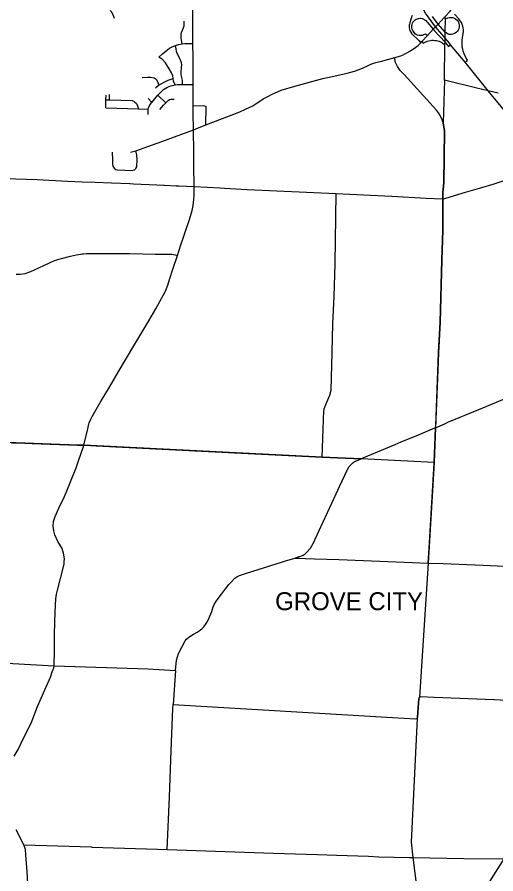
# Model space of a CAD drawing. Extents: x 1755200 to 1902939, y 644115 to 788070.
# Drawn here: x 1782951 to 1796306, y 677595 to 701476 of the extents above; entities that cross this region are included whole.
import ezdxf

# ---------------------------------------------------------------- set-up
doc = ezdxf.new("R2010")
doc.units = 0
for name, color, linetype in [('GM_X_City_Street', 7, 'Continuous'), ('GM_X_Corporation_Text', 7, 'Continuous'), ('GM_X_County_Road', 7, 'Continuous'), ('GM_X_Interchange_Ramps', 7, 'Continuous'), ('GM_X_Interstate_Route', 7, 'Continuous'), ('GM_X_Township', 7, 'Continuous'), ('GM_X_Township_Road', 7, 'Continuous'), ('GM_X_US_Route', 7, 'Continuous')]:
    doc.layers.add(name, color=color, linetype=linetype)

msp = doc.modelspace()

# ---------------------------------------------------------------- linework, layer by layer
at = {"layer": 'GM_X_City_Street'}
for points in [[(1787860, 699018), (1787858, 699597), (1787860, 700358), (1787857, 700738), (1787852, 701242), (1787854, 701665), (1787855, 702336), (1787857, 703006), (1787855, 703286)], [(1793741, 700437), (1793752, 700441), (1793845, 700487), (1793927, 700535), (1794011, 700592), (1794134, 700688), (1794214, 700764), (1794240, 700797), (1794396, 700960), (1794557, 701136), (1794621, 701208), (1794693, 701283), (1794864, 701465), (1794893, 701495), (1795030, 701641), (1795063, 701678), (1795126, 701755), (1795195, 701840), (1795261, 701935), (1795301, 702007), (1795333, 702066)], [(1785663, 701434), (1785634, 701537), (1785581, 701622), (1785551, 701659)], [(1787558, 700734), (1787537, 700830), (1787529, 700891), (1787526, 700956), (1787530, 701005), (1787537, 701045), (1787566, 701117), (1787607, 701233), (1787615, 701295), (1787613, 701362)], [(1786904, 700363), (1787009, 700452), (1787107, 700539), (1787201, 700608), (1787291, 700659), (1787371, 700689), (1787457, 700713), (1787558, 700734), (1787630, 700741), (1787857, 700738)], [(1787568, 699600), (1787565, 699703), (1787558, 699757), (1787529, 699867), (1787526, 699907), (1787530, 699946), (1787540, 700071), (1787544, 700150), (1787537, 700203), (1787516, 700260), (1787490, 700314), (1787410, 700486), (1787371, 700689)], [(1787874, 698335), (1788217, 698471), (1788682, 698648), (1789167, 698839), (1789320, 698907), (1789523, 699005), (1789815, 699194), (1789942, 699267), (1790064, 699333), (1790216, 699398), (1790319, 699438), (1790694, 699548), (1791479, 699763), (1791782, 699829), (1792162, 699917), (1792363, 699973), (1792488, 700015), (1792602, 700064), (1792727, 700122), (1792821, 700163), (1792957, 700208), (1793151, 700262), (1793486, 700349), (1793652, 700400), (1793741, 700437)], [(1787359, 699591), (1787316, 699688), (1787305, 699768), (1787296, 699835), (1787257, 699924), (1787193, 700037), (1787087, 700199), (1786996, 700308), (1786904, 700363)], [(1794824, 696413), (1794825, 696594), (1794834, 696685), (1794851, 696855), (1794873, 698294), (1794837, 698528), (1794811, 698613), (1794734, 698773), (1794654, 698882), (1793750, 699877), (1793637, 699992), (1793560, 700096), (1793541, 700135), (1793499, 700228), (1793486, 700349)], [(1786436, 699794), (1786590, 699806), (1786672, 699801), (1786772, 699784), (1786828, 699747), (1786867, 699684), (1786902, 699576)], [(1786813, 699503), (1786890, 699568), (1786902, 699576), (1786972, 699621), (1787067, 699672), (1787164, 699720), (1787305, 699768)], [(1786606, 698762), (1786608, 698906), (1786608, 698916), (1786623, 698964), (1786650, 699034), (1786706, 699100), (1786875, 699296), (1786878, 699299), (1787035, 699454), (1787143, 699521), (1787241, 699558), (1787359, 699591), (1787427, 699599), (1787568, 699600), (1787858, 699597)], [(1785424, 698946), (1785425, 699168), (1785432, 699299)], [(1785525, 699166), (1785529, 699315)], [(1786875, 699296), (1787102, 699091)], [(1785425, 699168), (1785525, 699166), (1786160, 699148), (1786228, 699113), (1786284, 699069), (1786311, 699004), (1786334, 698915)], [(1786602, 699211), (1786706, 699100)], [(1786932, 698898), (1787036, 699025), (1787102, 699091), (1787164, 699155), (1787197, 699177), (1787241, 699190), (1787265, 699190), (1787333, 699187)], [(1787874, 698334), (1787874, 698335), (1787863, 698796), (1787860, 699008), (1787860, 699018)], [(1787860, 699008), (1788180, 699002), (1788221, 698982)], [(1785424, 698946), (1786334, 698915), (1786608, 698906)], [(1788217, 698471), (1788221, 698982)], [(1786109, 697716), (1786264, 697748), (1786593, 697867), (1786985, 698008), (1787874, 698335)], [(1787878, 697701), (1787874, 698334)], [(1785601, 697716), (1785608, 697498), (1785608, 697405), (1785608, 697365), (1785620, 697318), (1785657, 697268), (1785707, 697231), (1785753, 697219), (1785960, 697210), (1786164, 697200), (1786225, 697219), (1786264, 697254), (1786292, 697299), (1786302, 697505), (1786292, 697627), (1786264, 697748)], [(1787886, 696753), (1787886, 696753), (1787877, 697338), (1787878, 697696), (1787878, 697701)], [(1794815, 696413), (1794824, 696413), (1794882, 696423), (1795150, 696503), (1795462, 696597), (1795846, 696710), (1796227, 696823), (1796396, 696877), (1796541, 696924)], [(1787465, 696773), (1787886, 696753)], [(1787581, 695318), (1787644, 695510), (1787755, 695837), (1787831, 696083), (1787865, 696227), (1787884, 696389), (1787886, 696506), (1787886, 696753)], [(1787886, 696753), (1788614, 696715), (1788733, 696708)], [(1788733, 696708), (1789370, 696675), (1791855, 696557), (1792612, 696521), (1793399, 696481), (1794364, 696432), (1794815, 696413)], [(1791515, 690529), (1791520, 690559), (1791534, 690600), (1791565, 690676), (1791675, 690939), (1791710, 691076), (1791741, 692131), (1791760, 692924), (1791791, 693686), (1791820, 694601), (1791855, 696557)], [(1794723, 692465), (1794750, 692977), (1794796, 694700), (1794822, 695537), (1794824, 696413)], [(1787206, 694162), (1787215, 694190), (1787299, 694452), (1787421, 694829), (1787518, 695126), (1787581, 695318)], [(1787268, 694866), (1787316, 694859), (1787360, 694848), (1787421, 694829)], [(1794627, 690096), (1794704, 692111), (1794706, 692149)], [(1794896, 690150), (1794967, 690182), (1795830, 690539), (1796659, 690885), (1796910, 690990), (1797053, 691047)], [(1791461, 689213), (1791511, 690507), (1791515, 690529)], [(1792546, 689167), (1792624, 689200), (1793496, 689565), (1793662, 689634), (1794151, 689836), (1794604, 690023)], [(1785153, 689525), (1789400, 689315)], [(1789400, 689315), (1791461, 689213), (1792546, 689167)], [(1791954, 688409), (1792155, 688846), (1792210, 688952), (1792312, 689056), (1792364, 689086), (1792418, 689112), (1792546, 689167)], [(1794416, 686257), (1794442, 686678)], [(1793981, 686274), (1794416, 686257)], [(1794416, 686257), (1794416, 686257), (1794840, 686242)], [(1796257, 682451), (1796936, 682422), (1798693, 682335), (1798738, 682332)]]:
    msp.add_lwpolyline(points, dxfattribs=at)
at = {"layer": 'GM_X_County_Road'}
for points in [[(1782535, 694298), (1782550, 695153), (1782591, 696469), (1782608, 696832), (1782612, 696920), (1782619, 696976), (1783507, 696946), (1784356, 696907), (1784769, 696885), (1785129, 696875), (1785584, 696857), (1786091, 696836), (1786195, 696829), (1786848, 696802), (1787044, 696794)], [(1787044, 696794), (1787062, 696793), (1787389, 696777), (1787465, 696773)], [(1782920, 694307), (1783033, 694312), (1783111, 694323), (1783176, 694333), (1783333, 694386), (1783575, 694498), (1783695, 694551), (1783871, 694632), (1783993, 694688), (1784059, 694711), (1784115, 694732), (1784191, 694752), (1784440, 694810), (1784605, 694851), (1784718, 694873), (1784755, 694880), (1784804, 694882), (1784877, 694883), (1785289, 694884), (1786094, 694888), (1786813, 694868), (1787193, 694865), (1787264, 694866), (1787268, 694866)], [(1786873, 693447), (1787091, 693837), (1787119, 693912), (1787157, 694004), (1787206, 694162)], [(1784810, 689542), (1784924, 689998), (1784946, 690089), (1784965, 690163), (1785009, 690269), (1785040, 690341), (1785080, 690412), (1785153, 690538), (1785300, 690784), (1785526, 691165), (1785771, 691576), (1786210, 692313), (1786624, 693006), (1786817, 693347), (1786873, 693447)], [(1794706, 692149), (1794723, 692465)], [(1794586, 689044), (1794587, 689062), (1794625, 690031), (1794627, 690096)], [(1794604, 690023), (1794625, 690031), (1794896, 690150)], [(1783994, 684036), (1783992, 684283), (1784016, 684901), (1784030, 685257), (1784047, 685387), (1784078, 685503), (1784164, 685827), (1784260, 686223), (1784265, 686288), (1784269, 686376), (1784248, 686538), (1784203, 686665), (1784090, 686862), (1784007, 687049), (1783978, 687155), (1783954, 687283), (1783967, 687414), (1784008, 687552), (1784116, 687791), (1784268, 688115), (1784422, 688479), (1784595, 688909), (1784677, 689137), (1784792, 689481), (1784810, 689542)], [(1794442, 686678), (1794586, 689044)], [(1790666, 686385), (1790823, 686437), (1790897, 686460), (1790932, 686479), (1790985, 686514), (1791027, 686555), (1791131, 686674), (1791171, 686741), (1791221, 686822), (1791370, 687150), (1791852, 688189), (1791946, 688390), (1791954, 688409)], [(1787370, 683265), (1787401, 683551), (1787456, 683739), (1787636, 684086), (1787674, 684134), (1787739, 684192), (1787871, 684273), (1787970, 684334), (1788058, 684389), (1788112, 684430), (1788161, 684480), (1788205, 684546), (1788246, 684599), (1788279, 684664), (1788324, 684774), (1788380, 684912), (1788414, 685012), (1788449, 685101), (1788493, 685180), (1788559, 685269), (1788649, 685393), (1788760, 685544), (1788858, 685658), (1788920, 685725), (1789020, 685835), (1789083, 685878), (1789153, 685914), (1789348, 685977), (1790506, 686338), (1790666, 686385), (1790747, 686392), (1790825, 686394), (1790996, 686388), (1791243, 686379), (1791923, 686354), (1793981, 686274)], [(1794840, 686242), (1795948, 686200), (1796943, 686156), (1797495, 686135), (1797838, 686120), (1797860, 686120)], [(1773735, 684084), (1773770, 684068), (1773823, 684048), (1774075, 684022), (1774528, 683999), (1776435, 683842), (1776845, 683820), (1777912, 683762), (1778599, 683726), (1779300, 683688), (1780237, 683632), (1781070, 683572), (1781206, 683562), (1782831, 683463), (1783987, 683396)], [(1783987, 683396), (1783995, 683816), (1783994, 684031), (1783994, 684036)], [(1782868, 680877), (1782977, 681061), (1783111, 681340), (1783339, 681797), (1783524, 682256), (1783728, 682725), (1783880, 683080), (1783933, 683226), (1783978, 683340), (1783987, 683396)], [(1783987, 683396), (1786602, 683307), (1787370, 683265)], [(1787370, 683265), (1787303, 682313)], [(1787303, 682313), (1793425, 681955), (1794075, 681916), (1794108, 681930), (1794122, 681965), (1794160, 682486), (1794171, 682523), (1794199, 682540)], [(1794199, 682540), (1794203, 682542), (1794589, 682521), (1796245, 682451), (1796257, 682451)], [(1782799, 672895), (1783258, 672938), (1783298, 672959), (1783324, 673007), (1783374, 673235), (1783468, 673837), (1783535, 674036), (1783550, 674333), (1783542, 674374), (1783468, 674540), (1783387, 674689), (1783347, 674762), (1783328, 674832), (1783304, 674932), (1783299, 675075), (1783336, 675721), (1783338, 675938), (1783324, 676240), (1783261, 677156), (1783230, 677651), (1783198, 678124), (1783187, 678273), (1783142, 678403), (1782923, 678824)], [(1783142, 678403), (1783772, 678383), (1783773, 678383)], [(1783773, 678383), (1785029, 678344), (1785034, 678343), (1785035, 678343)], [(1785035, 678343), (1785949, 678314), (1786867, 678280), (1787140, 678276)], [(1787140, 678276), (1790103, 678176), (1791332, 678132), (1791862, 678115), (1792754, 678086), (1793042, 678073), (1793899, 678052)], [(1793899, 678052), (1793990, 678050), (1795408, 678027), (1796540, 678009)]]:
    msp.add_lwpolyline(points, dxfattribs=at)
at = {"layer": 'GM_X_Interchange_Ramps'}
for points in [[(1793970, 701523), (1793946, 701449), (1793904, 701316), (1793894, 701280), (1793889, 701248), (1793887, 701215), (1793889, 701176), (1793896, 701136), (1793907, 701102), (1793930, 701053), (1793961, 701008), (1794155, 700823), (1794214, 700764)], [(1794396, 700960), (1794346, 701005), (1794285, 700979), (1794251, 700968), (1794207, 700965), (1794166, 700963), (1794124, 700972), (1794096, 700983), (1794061, 701004), (1794025, 701048), (1794004, 701074), (1793986, 701105), (1793972, 701139), (1793963, 701176), (1793960, 701207), (1793962, 701240), (1793969, 701273), (1793980, 701304), (1793993, 701331), (1794009, 701353), (1794029, 701376), (1794052, 701397), (1794084, 701417), (1794115, 701431), (1794148, 701440), (1794183, 701445), (1794215, 701444), (1794247, 701439), (1794271, 701432), (1794348, 701378), (1794401, 701326), (1794557, 701136), (1794589, 701100), (1794887, 700776), (1794904, 700755), (1794987, 700655), (1795043, 700707)], [(1794864, 701465), (1794896, 701429), (1794961, 701453), (1795009, 701470), (1795064, 701470), (1795109, 701463), (1795155, 701445), (1795193, 701420), (1795226, 701389), (1795253, 701352), (1795272, 701311), (1795283, 701263), (1795284, 701207), (1795271, 701148), (1795254, 701112), (1795229, 701076), (1795195, 701044), (1795150, 701015), (1795104, 700999), (1795066, 700992), (1795031, 700992), (1794998, 700996), (1794974, 701002), (1794928, 701028), (1794891, 701056), (1794693, 701283), (1794540, 701490)], [(1795445, 700217), (1795516, 700278), (1795472, 700352), (1795422, 700454), (1795395, 700523), (1795380, 700580), (1795368, 700641), (1795363, 700706), (1795363, 700777), (1795370, 700834), (1795379, 700906), (1795389, 701012), (1795398, 701071), (1795399, 701124), (1795395, 701173), (1795384, 701227), (1795367, 701275), (1795345, 701323), (1795319, 701364), (1795291, 701401), (1795273, 701426), (1795154, 701558)], [(1794240, 700797), (1794282, 700754), (1794351, 700789), (1794389, 700804), (1794432, 700816), (1794478, 700826), (1794516, 700830), (1794555, 700831), (1794604, 700829), (1794649, 700822), (1794689, 700812), (1794722, 700802), (1794761, 700786), (1794796, 700768), (1794820, 700754), (1794866, 700723), (1794886, 700739), (1794904, 700755)]]:
    msp.add_lwpolyline(points, dxfattribs=at)
at = {"layer": 'GM_X_Interstate_Route'}
for points in [[(1794621, 701208), (1794347, 701585), (1794293, 701666)], [(1795008, 700749), (1794888, 700894), (1794797, 701005), (1794621, 701208)], [(1795043, 700707), (1795008, 700749)], [(1797609, 697576), (1796813, 698552), (1796095, 699426), (1795445, 700217), (1795043, 700707)]]:
    msp.add_lwpolyline(points, dxfattribs=at)
at = {"layer": 'GM_X_Township'}
for points in [[(1794587, 689062), (1792546, 689167), (1791461, 689213), (1784810, 689542), (1784632, 689548), (1783167, 689596), (1782688, 689618), (1780628, 689706), (1776861, 692396), (1776156, 692877), (1775926, 693071), (1769123, 697982), (1765814, 700371), (1762103, 702170)], [(1796374, 699359), (1796095, 699426), (1795774, 699500), (1794871, 699722), (1794886, 700739), (1794887, 700776), (1794888, 700894), (1794891, 701056), (1794896, 701429), (1794893, 701495)], [(1794871, 699722), (1794837, 698528), (1794873, 698294), (1794851, 696855), (1794834, 696685), (1794825, 696594), (1794824, 696413), (1794822, 695537), (1794796, 694700), (1794750, 692977), (1794704, 692111), (1794625, 690031), (1794587, 689062), (1794416, 686257), (1794171, 682523), (1794160, 682486), (1794122, 681965), (1794108, 681930), (1793947, 678482), (1793990, 678050), (1794416, 674693)]]:
    msp.add_lwpolyline(points, dxfattribs=at)
at = {"layer": 'GM_X_Township_Road'}
for points in [[(1782793, 689613), (1783167, 689596), (1783370, 689590)], [(1783370, 689590), (1784632, 689548), (1784810, 689542), (1784839, 689541)], [(1784839, 689541), (1785153, 689525)], [(1787140, 678276), (1787198, 679744), (1787246, 681024), (1787298, 682207), (1787303, 682313)]]:
    msp.add_lwpolyline(points, dxfattribs=at)
at = {"layer": 'GM_X_US_Route'}
msp.add_lwpolyline([(1794369, 674621), (1794416, 674693), (1795452, 676291), (1796252, 677554), (1796540, 678009)], dxfattribs=at)

# ---------------------------------------------------------------- texts
at = {"layer": 'GM_X_Corporation_Text'}
msp.add_text('GROVE CITY', height=500, rotation=0, dxfattribs=at).set_placement((1790148, 684945))

doc.saveas('drawing.dxf')
